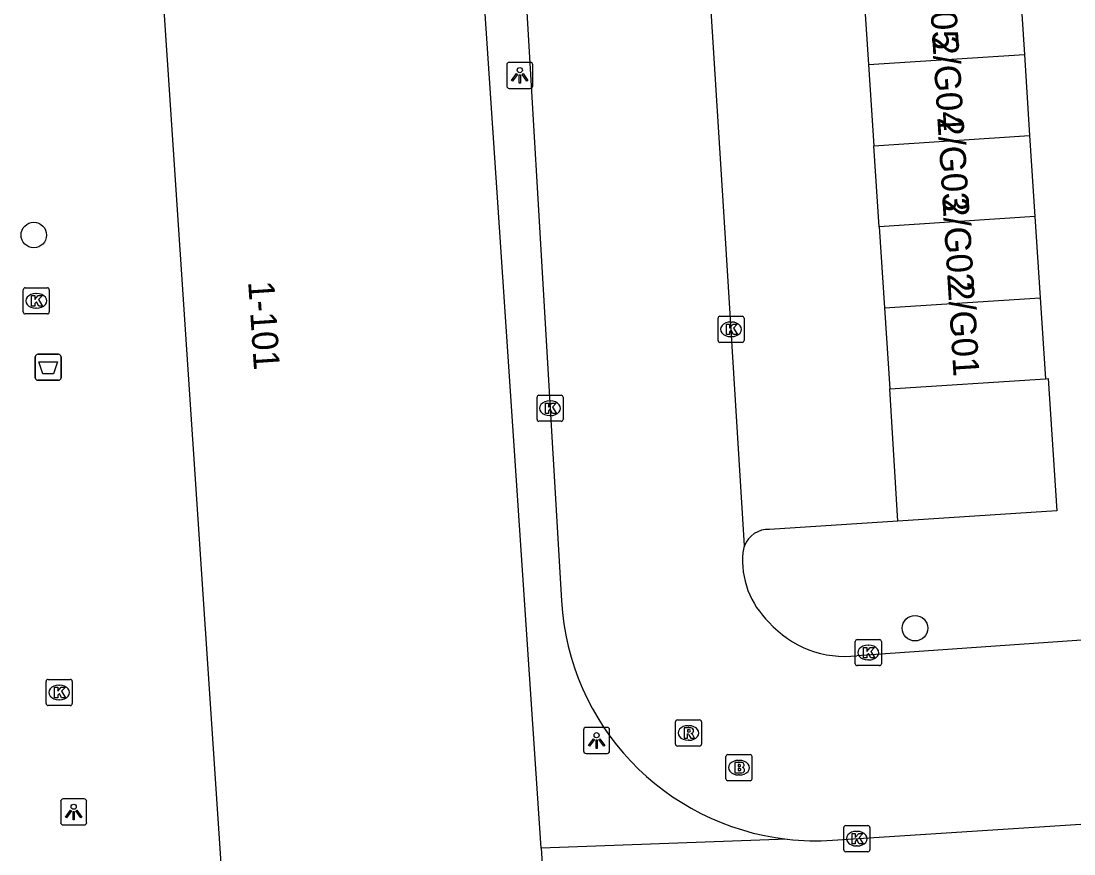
# Model space of a CAD drawing. Extents: x 159689 to 160786, y 387323 to 388339.
# Drawn here: x 160314.22 to 160354.58, y 387760.4 to 387792.33 of the extents above; entities that cross this region are included whole.
import ezdxf

# ---------------------------------------------------------------- set-up
doc = ezdxf.new("R2010")
doc.units = 0
for name, color, linetype in [('IMGEO_Afvalbak', 7, 'Continuous'), ('IMGEO_Boom', 7, 'Continuous'), ('IMGEO_Brandkraan', 7, 'Continuous'), ('IMGEO_Kolk', 7, 'Continuous'), ('IMGEO_Lichtpunt', 7, 'Continuous'), ('IMGEO_Pand', 7, 'Continuous'), ('IMGEO_Pand_nummerreeks', 7, 'Continuous'), ('IMGEO_Parkeervlak_open', 7, 'Continuous'), ('IMGEO_Rijbaan_lokaal_open', 7, 'Continuous'), ('IMGEO_Rioolput', 7, 'Continuous'), ('IMGEO_Voetpad_open', 7, 'Continuous')]:
    doc.layers.add(name, color=color, linetype=linetype)

msp = doc.modelspace()

# ---------------------------------------------------------------- linework, layer by layer
at = {"layer": 'IMGEO_Afvalbak'}
for p, q in [((160314.76, 387778.659), (160314.76, 387779.459)), ((160314.76, 387779.459), (160314.76, 387778.659)), ((160314.86, 387779.559), (160315.65, 387779.559)), ((160315.65, 387779.559), (160314.86, 387779.559)), ((160315.75, 387779.459), (160315.75, 387778.659)), ((160315.75, 387778.659), (160315.75, 387779.459)), ((160315.65, 387778.559), (160314.86, 387778.559)), ((160314.86, 387778.559), (160315.65, 387778.559))]:
    msp.add_line(p, q, dxfattribs=at)
msp.add_lwpolyline([(160314.903, 387779.273), (160315.607, 387779.273), (160315.458, 387778.803), (160315.052, 387778.803), (160314.903, 387779.273)], dxfattribs=at)
for centre, start, end in [((160314.86, 387779.459), 90, 180), ((160314.86, 387779.459), 90, 180), ((160315.65, 387779.459), 0, 90), ((160315.65, 387779.459), 360, 90), ((160314.86, 387778.659), 180, 270), ((160314.86, 387778.659), 180, 270), ((160315.65, 387778.659), 270, 0), ((160315.65, 387778.659), 270, 0)]:
    msp.add_arc(centre, 0.1, start, end, dxfattribs=at)
at = {"layer": 'IMGEO_Boom'}
for centre in [(160314.705, 387784.129), (160348.491, 387769.055)]:
    msp.add_circle(centre, 0.489, dxfattribs=at)
at = {"layer": 'IMGEO_Brandkraan'}
for p, q in [((160341.24, 387763.281), (160341.24, 387764.133)), ((160341.315, 387764.207), (160342.167, 387764.207)), ((160342.241, 387764.133), (160342.241, 387763.281)), ((160341.728, 387763.987), (160341.753, 387763.987)), ((160342.167, 387763.207), (160341.315, 387763.207)), ((160341.751, 387763.427), (160341.726, 387763.427))]:
    msp.add_line(p, q, dxfattribs=at)
for points in [[(160341.24, 387763.281), (160341.24, 387764.133)], [(160341.315, 387764.207), (160342.167, 387764.207)], [(160342.241, 387764.133), (160342.241, 387763.281)], [(160341.588, 387763.907), (160341.588, 387763.507), (160341.801, 387763.507)], [(160341.819, 387763.907), (160341.588, 387763.907)], [(160341.767, 387763.826), (160341.713, 387763.826), (160341.713, 387763.75)], [(160341.713, 387763.75), (160341.766, 387763.75)], [(160341.775, 387763.674), (160341.713, 387763.674), (160341.713, 387763.593)], [(160342.167, 387763.207), (160341.315, 387763.207)], [(160341.713, 387763.593), (160341.775, 387763.593)]]:
    msp.add_lwpolyline(points, dxfattribs=at)
for centre, radius, start, end in [((160341.317, 387764.131), 0.0765, 91.552, 178.448), ((160341.317, 387764.131), 0.0765, 91.552, 178.448), ((160342.165, 387764.131), 0.0765, 1.552, 88.448), ((160342.165, 387764.131), 0.0765, 1.552, 88.448), ((160341.768, 387763.788), 0.0379, 267.8285, 90.9355), ((160341.776, 387763.633), 0.0404, 269.8759, 90.5077), ((160341.823, 387763.762), 0.145, 59.4692, 91.5367), ((160341.848, 387763.809), 0.0922, 285.5137, 58.1501), ((160341.853, 387763.617), 0.105, 301.3115, 78.989), ((160341.317, 387763.283), 0.0765, 181.552, 268.448), ((160341.317, 387763.283), 0.0765, 181.552, 268.448), ((160341.807, 387763.758), 0.251, 268.6676, 293.5347), ((160342.165, 387763.283), 0.0765, 271.552, 358.448), ((160342.165, 387763.283), 0.0765, 271.552, 358.448)]:
    msp.add_arc(centre, radius, start, end, dxfattribs=at)
for centre, major_axis, ratio, start_param, end_param in [((160341.727, 387763.707), (-0.387, 0.002), 0.722429, 4.712389, 7.853982), ((160341.752, 387763.707), (-0.39, 0.002), 0.717154, 1.570796, 4.712389)]:
    msp.add_ellipse(centre, major_axis=major_axis, ratio=ratio, start_param=start_param, end_param=end_param, dxfattribs=at)
at = {"layer": 'IMGEO_Kolk'}
for p, q in [((160314.298, 387781.179), (160314.298, 387782.031)), ((160314.373, 387782.105), (160315.225, 387782.105)), ((160314.786, 387781.885), (160314.811, 387781.885)), ((160315.299, 387782.031), (160315.299, 387781.179)), ((160315.225, 387781.105), (160314.373, 387781.105)), ((160314.809, 387781.325), (160314.784, 387781.325)), ((160341.014, 387781.015), (160341.866, 387781.015)), ((160340.939, 387780.089), (160340.939, 387780.941)), ((160341.427, 387780.795), (160341.452, 387780.795)), ((160341.94, 387780.941), (160341.94, 387780.089)), ((160341.45, 387780.235), (160341.425, 387780.235)), ((160341.866, 387780.015), (160341.014, 387780.015)), ((160333.998, 387777.061), (160333.998, 387777.913)), ((160334.073, 387777.987), (160334.925, 387777.987)), ((160334.486, 387777.767), (160334.511, 387777.767)), ((160334.999, 387777.913), (160334.999, 387777.061)), ((160334.925, 387776.987), (160334.073, 387776.987)), ((160334.509, 387777.207), (160334.484, 387777.207)), ((160346.201, 387767.693), (160346.201, 387768.545)), ((160346.276, 387768.619), (160347.128, 387768.619)), ((160347.202, 387768.545), (160347.202, 387767.693)), ((160346.689, 387768.399), (160346.714, 387768.399)), ((160346.712, 387767.839), (160346.687, 387767.839)), ((160347.128, 387767.619), (160346.276, 387767.619)), ((160315.177, 387766.165), (160315.177, 387767.017)), ((160315.252, 387767.091), (160316.104, 387767.091)), ((160315.665, 387766.871), (160315.69, 387766.871)), ((160316.178, 387767.017), (160316.178, 387766.165)), ((160316.104, 387766.091), (160315.252, 387766.091)), ((160315.688, 387766.311), (160315.663, 387766.311)), ((160345.759, 387760.56), (160345.759, 387761.412)), ((160345.834, 387761.486), (160346.686, 387761.486)), ((160346.247, 387761.266), (160346.272, 387761.266)), ((160346.76, 387761.412), (160346.76, 387760.56)), ((160346.686, 387760.486), (160345.834, 387760.486)), ((160346.27, 387760.706), (160346.245, 387760.706))]:
    msp.add_line(p, q, dxfattribs=at)
for points in [[(160314.298, 387781.179), (160314.298, 387782.031)], [(160314.373, 387782.105), (160315.225, 387782.105)], [(160314.619, 387781.805), (160314.742, 387781.805), (160314.742, 387781.654), (160314.872, 387781.805), (160315.036, 387781.805), (160314.89, 387781.654), (160315.043, 387781.405), (160314.891, 387781.405), (160314.806, 387781.569), (160314.742, 387781.502), (160314.742, 387781.405), (160314.619, 387781.405), (160314.619, 387781.805)], [(160315.299, 387782.031), (160315.299, 387781.179)], [(160315.225, 387781.105), (160314.373, 387781.105)], [(160341.014, 387781.015), (160341.866, 387781.015)], [(160340.939, 387780.089), (160340.939, 387780.941)], [(160341.26, 387780.715), (160341.383, 387780.715), (160341.383, 387780.564), (160341.513, 387780.715), (160341.677, 387780.715), (160341.531, 387780.564), (160341.684, 387780.315), (160341.532, 387780.315), (160341.447, 387780.479), (160341.383, 387780.412), (160341.383, 387780.315), (160341.26, 387780.315), (160341.26, 387780.715)], [(160341.94, 387780.941), (160341.94, 387780.089)], [(160341.866, 387780.015), (160341.014, 387780.015)], [(160333.998, 387777.061), (160333.998, 387777.913)], [(160334.073, 387777.987), (160334.925, 387777.987)], [(160334.999, 387777.913), (160334.999, 387777.061)], [(160334.319, 387777.687), (160334.442, 387777.687), (160334.442, 387777.536), (160334.572, 387777.687), (160334.736, 387777.687), (160334.59, 387777.536), (160334.743, 387777.287), (160334.591, 387777.287), (160334.506, 387777.451), (160334.442, 387777.384), (160334.442, 387777.287), (160334.319, 387777.287), (160334.319, 387777.687)], [(160334.925, 387776.987), (160334.073, 387776.987)], [(160346.201, 387767.693), (160346.201, 387768.545)], [(160346.276, 387768.619), (160347.128, 387768.619)], [(160347.202, 387768.545), (160347.202, 387767.693)], [(160346.522, 387768.319), (160346.645, 387768.319), (160346.645, 387768.168), (160346.775, 387768.319), (160346.939, 387768.319), (160346.793, 387768.168), (160346.946, 387767.919), (160346.794, 387767.919), (160346.709, 387768.083), (160346.645, 387768.016), (160346.645, 387767.919), (160346.522, 387767.919), (160346.522, 387768.319)], [(160347.128, 387767.619), (160346.276, 387767.619)], [(160315.177, 387766.165), (160315.177, 387767.017)], [(160315.252, 387767.091), (160316.104, 387767.091)], [(160316.178, 387767.017), (160316.178, 387766.165)], [(160315.498, 387766.791), (160315.621, 387766.791), (160315.621, 387766.64), (160315.751, 387766.791), (160315.915, 387766.791), (160315.769, 387766.64), (160315.922, 387766.391), (160315.77, 387766.391), (160315.685, 387766.555), (160315.621, 387766.488), (160315.621, 387766.391), (160315.498, 387766.391), (160315.498, 387766.791)], [(160316.104, 387766.091), (160315.252, 387766.091)], [(160345.759, 387760.56), (160345.759, 387761.412)], [(160345.834, 387761.486), (160346.686, 387761.486)], [(160346.08, 387761.186), (160346.203, 387761.186), (160346.203, 387761.035), (160346.333, 387761.186), (160346.497, 387761.186), (160346.351, 387761.035), (160346.504, 387760.786), (160346.352, 387760.786), (160346.267, 387760.95), (160346.203, 387760.883), (160346.203, 387760.786), (160346.08, 387760.786), (160346.08, 387761.186)], [(160346.76, 387761.412), (160346.76, 387760.56)], [(160346.686, 387760.486), (160345.834, 387760.486)]]:
    msp.add_lwpolyline(points, dxfattribs=at)
for centre, start, end in [((160314.375, 387782.029), 91.552, 178.448), ((160314.375, 387782.029), 91.552, 178.448), ((160315.223, 387782.029), 1.552, 88.448), ((160315.223, 387782.029), 1.552, 88.448), ((160314.375, 387781.181), 181.552, 268.448), ((160314.375, 387781.181), 181.552, 268.448), ((160315.223, 387781.181), 271.552, 358.448), ((160315.223, 387781.181), 271.552, 358.448), ((160341.016, 387780.939), 91.552, 178.448), ((160341.016, 387780.939), 91.552, 178.448), ((160341.864, 387780.939), 1.552, 88.448), ((160341.864, 387780.939), 1.552, 88.448), ((160341.016, 387780.091), 181.552, 268.448), ((160341.016, 387780.091), 181.552, 268.448), ((160341.864, 387780.091), 271.552, 358.448), ((160341.864, 387780.091), 271.552, 358.448), ((160334.075, 387777.911), 91.552, 178.448), ((160334.075, 387777.911), 91.552, 178.448), ((160334.923, 387777.911), 1.552, 88.448), ((160334.923, 387777.911), 1.552, 88.448), ((160334.075, 387777.063), 181.552, 268.448), ((160334.075, 387777.063), 181.552, 268.448), ((160334.923, 387777.063), 271.552, 358.448), ((160334.923, 387777.063), 271.552, 358.448), ((160346.278, 387768.543), 91.552, 178.448), ((160346.278, 387768.543), 91.552, 178.448), ((160347.126, 387768.543), 1.552, 88.448), ((160347.126, 387768.543), 1.552, 88.448), ((160346.278, 387767.695), 181.552, 268.448), ((160346.278, 387767.695), 181.552, 268.448), ((160347.126, 387767.695), 271.552, 358.448), ((160347.126, 387767.695), 271.552, 358.448), ((160315.254, 387767.015), 91.552, 178.448), ((160315.254, 387767.015), 91.552, 178.448), ((160316.102, 387767.015), 1.552, 88.448), ((160316.102, 387767.015), 1.552, 88.448), ((160315.254, 387766.167), 181.552, 268.448), ((160315.254, 387766.167), 181.552, 268.448), ((160316.102, 387766.167), 271.552, 358.448), ((160316.102, 387766.167), 271.552, 358.448), ((160345.836, 387761.41), 91.552, 178.448), ((160345.836, 387761.41), 91.552, 178.448), ((160346.684, 387761.41), 1.552, 88.448), ((160346.684, 387761.41), 1.552, 88.448), ((160345.836, 387760.562), 181.552, 268.448), ((160345.836, 387760.562), 181.552, 268.448), ((160346.684, 387760.562), 271.552, 358.448), ((160346.684, 387760.562), 271.552, 358.448)]:
    msp.add_arc(centre, 0.0765, start, end, dxfattribs=at)
for centre, major_axis, ratio, start_param, end_param in [((160314.785, 387781.605), (-0.387, 0.002), 0.722429, 4.712389, 7.853982), ((160314.81, 387781.605), (-0.39, 0.002), 0.717154, 1.570796, 4.712389), ((160341.426, 387780.515), (-0.387, 0.002), 0.722429, 4.712389, 7.853982), ((160341.451, 387780.515), (-0.39, 0.002), 0.717154, 1.570796, 4.712389), ((160334.485, 387777.487), (-0.387, 0.002), 0.722429, 4.712389, 7.853982), ((160334.51, 387777.487), (-0.39, 0.002), 0.717154, 1.570796, 4.712389), ((160346.688, 387768.119), (-0.387, 0.002), 0.722429, 4.712389, 7.853982), ((160346.713, 387768.119), (-0.39, 0.002), 0.717154, 1.570796, 4.712389), ((160315.664, 387766.591), (-0.387, 0.002), 0.722429, 4.712389, 7.853982), ((160315.689, 387766.591), (-0.39, 0.002), 0.717154, 1.570796, 4.712389), ((160346.246, 387760.986), (-0.387, 0.002), 0.722429, 4.712389, 7.853982), ((160346.271, 387760.986), (-0.39, 0.002), 0.717154, 1.570796, 4.712389)]:
    msp.add_ellipse(centre, major_axis=major_axis, ratio=ratio, start_param=start_param, end_param=end_param, dxfattribs=at)
at = {"layer": 'IMGEO_Lichtpunt'}
for p, q in [((160332.839, 387790.655), (160332.839, 387789.848)), ((160332.839, 387790.655), (160332.839, 387789.848)), ((160333.741, 387790.75), (160332.933, 387790.75)), ((160333.741, 387790.75), (160332.933, 387790.75)), ((160333.835, 387789.848), (160333.835, 387790.655)), ((160333.835, 387789.848), (160333.835, 387790.655)), ((160332.933, 387789.754), (160333.741, 387789.754)), ((160332.933, 387789.754), (160333.741, 387789.754)), ((160336.686, 387765.25), (160335.878, 387765.25)), ((160336.686, 387765.25), (160335.878, 387765.25)), ((160335.784, 387765.155), (160335.784, 387764.348)), ((160335.784, 387765.155), (160335.784, 387764.348)), ((160336.78, 387764.348), (160336.78, 387765.155)), ((160336.78, 387764.348), (160336.78, 387765.155)), ((160335.878, 387764.254), (160336.686, 387764.254)), ((160335.878, 387764.254), (160336.686, 387764.254)), ((160315.735, 387762.412), (160315.735, 387761.605)), ((160315.735, 387762.412), (160315.735, 387761.605)), ((160316.637, 387762.507), (160315.829, 387762.507)), ((160316.637, 387762.507), (160315.829, 387762.507)), ((160316.731, 387761.605), (160316.731, 387762.412)), ((160316.731, 387761.605), (160316.731, 387762.412)), ((160315.829, 387761.511), (160316.637, 387761.511)), ((160315.829, 387761.511), (160316.637, 387761.511))]:
    msp.add_line(p, q, dxfattribs=at)
for points in [[(160333.213, 387790.319), (160333.252, 387790.291), (160333.064, 387790.029), (160333.026, 387790.056), (160333.213, 387790.319)], [(160333.315, 387790.271), (160333.362, 387790.271), (160333.362, 387789.949), (160333.315, 387789.949), (160333.315, 387790.271)], [(160333.425, 387790.291), (160333.463, 387790.318), (160333.65, 387790.056), (160333.611, 387790.028), (160333.425, 387790.291)], [(160336.158, 387764.819), (160336.197, 387764.791), (160336.009, 387764.529), (160335.971, 387764.556), (160336.158, 387764.819)], [(160336.37, 387764.791), (160336.408, 387764.818), (160336.595, 387764.556), (160336.556, 387764.528), (160336.37, 387764.791)], [(160336.26, 387764.771), (160336.307, 387764.771), (160336.307, 387764.449), (160336.26, 387764.449), (160336.26, 387764.771)], [(160316.109, 387762.076), (160316.148, 387762.048), (160315.96, 387761.786), (160315.922, 387761.813), (160316.109, 387762.076)], [(160316.211, 387762.028), (160316.258, 387762.028), (160316.258, 387761.706), (160316.211, 387761.706), (160316.211, 387762.028)], [(160316.321, 387762.048), (160316.359, 387762.075), (160316.546, 387761.813), (160316.507, 387761.785), (160316.321, 387762.048)]]:
    msp.add_lwpolyline(points, dxfattribs=at)
for centre in [(160333.338, 387790.453), (160336.283, 387764.953), (160316.234, 387762.21)]:
    msp.add_circle(centre, 0.0994, dxfattribs=at)
for centre, start, end in [((160332.933, 387790.655), 90, 180), ((160332.933, 387790.655), 90, 180), ((160333.741, 387790.655), 0, 90), ((160333.741, 387790.655), 0, 90), ((160332.933, 387789.848), 180, 270), ((160332.933, 387789.848), 180, 270), ((160333.741, 387789.848), 270, 0), ((160333.741, 387789.848), 270, 360), ((160335.878, 387765.155), 90, 180), ((160335.878, 387765.155), 90, 180), ((160336.686, 387765.155), 0, 90), ((160336.686, 387765.155), 0, 90), ((160335.878, 387764.348), 180, 270), ((160335.878, 387764.348), 180, 270), ((160336.686, 387764.348), 270, 0), ((160336.686, 387764.348), 270, 360), ((160315.829, 387762.412), 90, 180), ((160315.829, 387762.412), 90, 180), ((160316.637, 387762.412), 0, 90), ((160316.637, 387762.412), 0, 90), ((160315.829, 387761.605), 180, 270), ((160315.829, 387761.605), 180, 270), ((160316.637, 387761.605), 270, 0), ((160316.637, 387761.605), 270, 360)]:
    msp.add_arc(centre, 0.0946, start, end, dxfattribs=at)
at = {"layer": 'IMGEO_Pand'}
for points in [[(160334.155, 387760.62), (160331.352, 387802.523)], [(160322.036, 387757.833), (160322.017, 387758.116), (160319.097, 387801.761)], [(160352.481, 387794.163), (160352.683, 387791.054)], [(160346.509, 387793.774), (160346.711, 387790.665)], [(160346.711, 387790.665), (160352.683, 387791.054)], [(160352.683, 387791.054), (160352.886, 387787.945)], [(160346.711, 387790.665), (160346.914, 387787.556)], [(160346.914, 387787.556), (160352.886, 387787.945)], [(160352.886, 387787.945), (160353.089, 387784.837)], [(160347.117, 387784.447), (160346.914, 387787.556)], [(160353.089, 387784.837), (160347.117, 387784.447)], [(160353.089, 387784.837), (160353.291, 387781.728)], [(160347.117, 387784.447), (160347.319, 387781.338)], [(160347.319, 387781.338), (160353.291, 387781.728)], [(160353.291, 387781.728), (160353.494, 387778.619)], [(160347.319, 387781.338), (160347.522, 387778.23)], [(160347.522, 387778.23), (160353.494, 387778.619)], [(160334.155, 387760.62), (160334.288, 387758.635)]]:
    msp.add_lwpolyline(points, dxfattribs=at)
at = {"layer": 'IMGEO_Parkeervlak_open'}
msp.add_lwpolyline([(160347.83, 387773.164), (160347.522, 387778.23)], dxfattribs=at)
at = {"layer": 'IMGEO_Rijbaan_lokaal_open'}
for points in [[(160341.952, 387772.208), (160341.198, 387784.423), (160339.882, 387805.311), (160338.406, 387828.202)], [(160332.752, 387806.497), (160332.954, 387803.761), (160334.935, 387770.099)], [(160358.917, 387768.881), (160346.266, 387768.001)], [(160345.325, 387760.926), (160375.86, 387762.898), (160379.928, 387763.183)]]:
    msp.add_lwpolyline(points, dxfattribs=at)
for centre, radius, start, end in [((160342.816, 387771.877), 0.925, 159.0409, 175.2336), ((160345.142, 387771.649), 3.263, 174.641, 226.4146), ((160344.685, 387770.671), 9.766, 183.3604, 263.5474), ((160345.806, 387771.862), 3.889, 221.4928, 276.7969), ((160344.687, 387770.734), 9.829, 263.5748, 273.7224)]:
    msp.add_arc(centre, radius, start, end, dxfattribs=at)
at = {"layer": 'IMGEO_Rioolput'}
for p, q in [((160339.306, 387764.612), (160339.306, 387765.464)), ((160339.381, 387765.538), (160340.233, 387765.538)), ((160339.794, 387765.318), (160339.819, 387765.318)), ((160340.307, 387765.464), (160340.307, 387764.612)), ((160340.233, 387764.538), (160339.381, 387764.538)), ((160339.817, 387764.758), (160339.792, 387764.758))]:
    msp.add_line(p, q, dxfattribs=at)
for points in [[(160339.306, 387764.612), (160339.306, 387765.464)], [(160339.381, 387765.538), (160340.233, 387765.538)], [(160339.895, 387765.236), (160339.643, 387765.238), (160339.643, 387764.838)], [(160340.307, 387765.464), (160340.307, 387764.612)], [(160339.643, 387764.838), (160339.767, 387764.838), (160339.767, 387765), (160339.778, 387765)], [(160339.821, 387765.157), (160339.767, 387765.157), (160339.767, 387765.076)], [(160339.767, 387765.076), (160339.819, 387765.076)], [(160339.825, 387764.971), (160339.896, 387764.838), (160340.036, 387764.838), (160339.971, 387764.964)], [(160340.233, 387764.538), (160339.381, 387764.538)]]:
    msp.add_lwpolyline(points, dxfattribs=at)
for centre, radius, start, end in [((160339.383, 387765.462), 0.0765, 91.552, 178.448), ((160339.383, 387765.462), 0.0765, 91.552, 178.448), ((160339.894, 387765.126), 0.109, 350.3612, 89.416), ((160340.231, 387765.462), 0.0765, 1.552, 88.448), ((160340.231, 387765.462), 0.0765, 1.552, 88.448), ((160339.777, 387764.947), 0.0533, 26.0293, 88.6989), ((160339.803, 387765.265), 0.19, 274.7715, 282.9687), ((160339.827, 387765.061), 0.0964, 77.0061, 93.1865), ((160339.841, 387765.118), 0.0378, 276.6634, 79.6772), ((160339.892, 387765.126), 0.112, 277.5842, 350.9817), ((160339.876, 387764.911), 0.108, 29.5134, 73.7905), ((160339.383, 387764.614), 0.0765, 181.552, 268.448), ((160339.383, 387764.614), 0.0765, 181.552, 268.448), ((160340.231, 387764.614), 0.0765, 271.552, 358.448), ((160340.231, 387764.614), 0.0765, 271.552, 358.448)]:
    msp.add_arc(centre, radius, start, end, dxfattribs=at)
for centre, major_axis, ratio, start_param, end_param in [((160339.793, 387765.038), (-0.387, 0.002), 0.722429, 4.712389, 7.853982), ((160339.818, 387765.038), (-0.39, 0.002), 0.717154, 1.570796, 4.712389)]:
    msp.add_ellipse(centre, major_axis=major_axis, ratio=ratio, start_param=start_param, end_param=end_param, dxfattribs=at)
at = {"layer": 'IMGEO_Voetpad_open'}
for points in [[(160353.494, 387778.619), (160353.599, 387778.626), (160353.929, 387773.561), (160347.83, 387773.164)], [(160347.83, 387773.164), (160342.911, 387772.843)], [(160343.587, 387760.967), (160334.155, 387760.62)]]:
    msp.add_lwpolyline(points, dxfattribs=at)
msp.add_arc((160342.868, 387771.866), 0.978, 87.4737, 159.5472, dxfattribs=at)

# ---------------------------------------------------------------- texts
at = {"layer": 'IMGEO_Pand_nummerreeks'}
for s, rotation, p in [('2/G05', 273.6085, (160348.953, 387794.845)), ('2/G04', 273.6085, (160349.149, 387791.74)), ('2/G03', 273.6085, (160349.345, 387788.636)), ('2/G02', 273.6085, (160349.54, 387785.537)), ('1-101', 273.8271, (160322.922, 387782.341)), ('2/G01', 273.6085, (160349.743, 387782.316))]:
    msp.add_text(s, height=1, rotation=rotation, dxfattribs=at).set_placement(p)

doc.saveas('drawing.dxf')
